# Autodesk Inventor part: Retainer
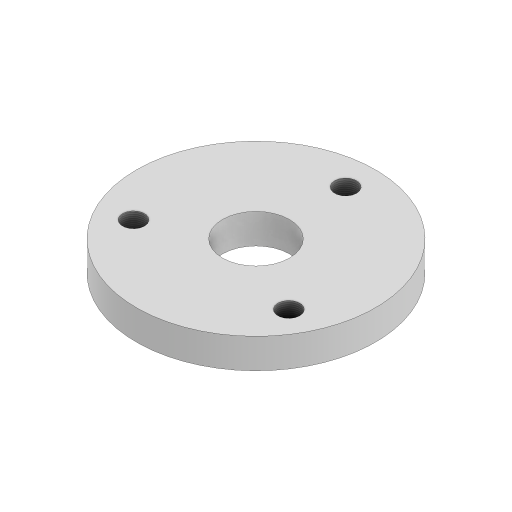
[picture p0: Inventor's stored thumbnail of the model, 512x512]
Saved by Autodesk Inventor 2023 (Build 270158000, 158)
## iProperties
Created: 2019-03
Part Number: Retainer
Material: Generic
Document SubType Name: Modeling
Designer: LENOVO-CADCIM
Density: 1 g/cm^3
Appearance: Default
Author: LENOVO-CADCIM
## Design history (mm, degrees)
sketch "Sketch1" dims "d1" = 150
  geometry: C1 r 100 at (0, 0); 3 further points
  constraints: 2 coincident, 1 centre point, 1 vertical alignment, 2 other
  dimensions: "d0" = 200 diameter of C1
extrude "Extrusion1" new body sketch "Sketch1" stored distance "d2" = 25; taper "d3" = 0 deg
sketch "Sketch2" dims "d4" = 150
  geometry: 3 further points
  constraints: 1 coincident, 1 vertical alignment, 2 other
hole "Hole1" sketch "Sketch2" at (0, 75) diameter "d5" = 18.376; stored, may be unused: countersink angle "d9" = 90 deg, drill point angle "d11" = 118 deg; dims "d6" = 40, "d7" = 4.4, "d8" = 2, "d10" = 47.3
pattern_circular "Circular Pattern1" dims angle "d13" = 360 deg
sketch "Sketch3"
  geometry: C1 r 28 at (0, 0); 1 further point
  constraints: 1 centre point, 1 coincident
  dimensions: "d15" = 56 diameter of C1
extrude "Extrusion2" cut sketch "Sketch3" distance "d16" = 25; taper "d17" = 0 deg
body "Solid1"
